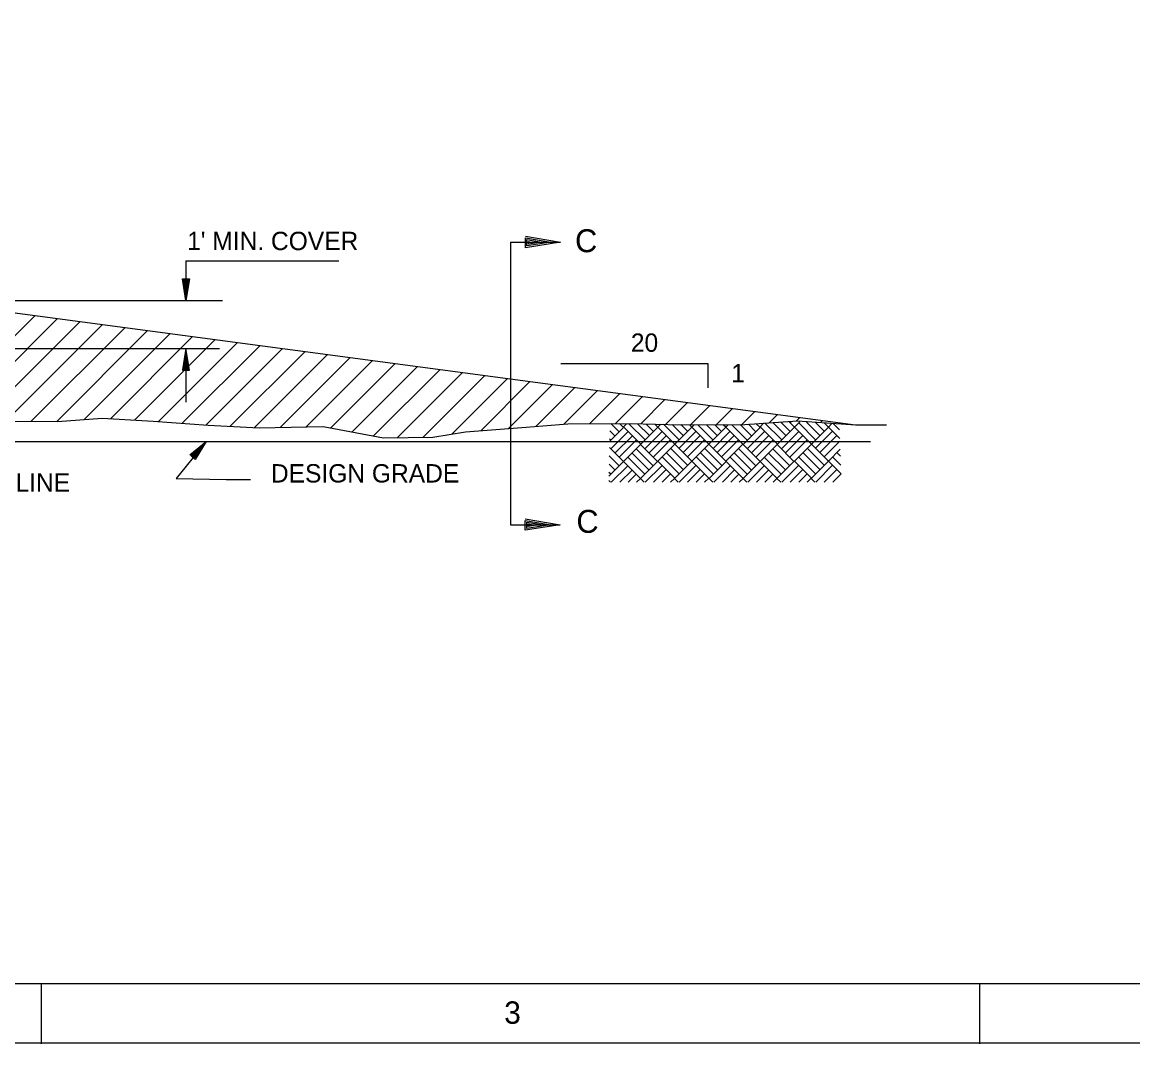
# Model space of a CAD drawing. Extents: x 2127959 to 2137375, y 2146193 to 2153470.
# Drawn here: x 2131601 to 2133592, y 2146193 to 2148025 of the extents above; entities that cross this region are included whole.
import ezdxf

# ---------------------------------------------------------------- set-up
doc = ezdxf.new("R2010")
doc.units = 0
for name, color, linetype in [('Level 1', 7, 'Continuous'), ('Level 3', 7, 'Continuous'), ('Level 5', 7, 'Continuous'), ('Level 50', 7, 'Continuous'), ('Level 63', 7, 'Continuous')]:
    doc.layers.add(name, color=color, linetype=linetype)

msp = doc.modelspace()

# ---------------------------------------------------------------- linework, layer by layer
at = {"layer": 'Level 1'}
for p, q in [((2131420.849, 2147525.847), (2133094.565, 2147302.516)), ((2129371.61, 2147272.911), (2133121.44, 2147272.911)), ((2128280.166, 2146300.478), (2136678.776, 2146300.478)), ((2131635.561, 2146192.625), (2131635.561, 2146300.478)), ((2133317.499, 2146192.626), (2133317.479, 2146300.478))]:
    msp.add_line(p, q, dxfattribs=at)
msp.add_lwpolyline([(2127959.193, 2153469.025), (2137374.681, 2153469.025), (2137374.681, 2146193.484), (2127959.193, 2146193.484)], close=True, dxfattribs=at)
at = {"layer": 'Level 3'}
for p, q in [((2131894.299, 2147597.059), (2131894.299, 2147525.847)), ((2131894.299, 2147597.059), (2132168.386, 2147597.059)), ((2131887.835, 2147564.595), (2131900.751, 2147564.595)), ((2131894.299, 2147525.847), (2131887.835, 2147564.595)), ((2131893.695, 2147563.956), (2131888.715, 2147564.052)), ((2131888.715, 2147564.052), (2131893.682, 2147533.841)), ((2131893.682, 2147563.213), (2131889.683, 2147563.324)), ((2131889.683, 2147563.324), (2131893.06, 2147541.295)), ((2131892.938, 2147562.359), (2131890.63, 2147562.448)), ((2131890.63, 2147562.448), (2131892.215, 2147551.348)), ((2131892.215, 2147551.348), (2131892.026, 2147561.706)), ((2131893.06, 2147541.295), (2131892.938, 2147562.359)), ((2131893.682, 2147533.841), (2131893.682, 2147563.213)), ((2131894.299, 2147525.847), (2131894.299, 2147564.595)), ((2131900.751, 2147564.595), (2131894.299, 2147525.847)), ((2131899.902, 2147563.937), (2131894.887, 2147533.753)), ((2131894.887, 2147533.753), (2131895.043, 2147563.205)), ((2131895.024, 2147564.01), (2131899.902, 2147563.937)), ((2131895.043, 2147563.205), (2131898.989, 2147563.077)), ((2131898.989, 2147563.077), (2131895.507, 2147541.148)), ((2131895.507, 2147541.148), (2131895.819, 2147562.373)), ((2131895.819, 2147562.373), (2131898.077, 2147562.382)), ((2131898.077, 2147562.382), (2131896.351, 2147551.367)), ((2131896.351, 2147551.367), (2131896.506, 2147561.72)), ((2131480.569, 2147525.847), (2131959.901, 2147525.847)), ((2131308.441, 2147439.647), (2131954.262, 2147439.647)), ((2131894.299, 2147439.647), (2131887.835, 2147400.893)), ((2131888.715, 2147401.44), (2131893.682, 2147431.65)), ((2131893.682, 2147431.65), (2131893.682, 2147402.277)), ((2131894.299, 2147439.647), (2131894.299, 2147343.107)), ((2131894.299, 2147439.647), (2131894.299, 2147400.893)), ((2131900.751, 2147400.893), (2131894.299, 2147439.647)), ((2131899.902, 2147401.557), (2131894.887, 2147431.738)), ((2131894.887, 2147431.738), (2131895.043, 2147402.288)), ((2131889.683, 2147402.166), (2131893.06, 2147424.198)), ((2131890.63, 2147403.041), (2131892.215, 2147414.142)), ((2131892.215, 2147414.142), (2131892.026, 2147403.786)), ((2131893.06, 2147424.198), (2131892.938, 2147403.133)), ((2131898.989, 2147402.417), (2131895.507, 2147424.345)), ((2131895.507, 2147424.345), (2131895.819, 2147403.116)), ((2131898.077, 2147403.107), (2131896.351, 2147414.125)), ((2131896.351, 2147414.125), (2131896.506, 2147403.773)), ((2132566.189, 2147412.463), (2132829.807, 2147412.463)), ((2132829.807, 2147412.463), (2132829.807, 2147369.047)), ((2131887.835, 2147400.893), (2131900.751, 2147400.893)), ((2131893.695, 2147401.534), (2131888.715, 2147401.44)), ((2131893.682, 2147402.277), (2131889.683, 2147402.166)), ((2131892.938, 2147403.133), (2131890.63, 2147403.041)), ((2131895.024, 2147401.481), (2131899.902, 2147401.557)), ((2131895.043, 2147402.288), (2131898.989, 2147402.417)), ((2131895.819, 2147403.116), (2131898.077, 2147403.107))]:
    msp.add_line(p, q, dxfattribs=at)
msp.add_lwpolyline([(2131930.575, 2147272.911), (2131876.766, 2147206.284), (2131966.089, 2147204.876), (2132009.879, 2147204.876)], dxfattribs=at)
at = {"layer": 'Level 5'}
for p, q in [((2131427.918, 2147302.868), (2131623.818, 2147498.766)), ((2131478.14, 2147307.381), (2131664.145, 2147493.383)), ((2131525.448, 2147308.965), (2131704.468, 2147488.002)), ((2131571.321, 2147309.125), (2131744.812, 2147482.62)), ((2131616.941, 2147309.031), (2131785.136, 2147477.238)), ((2131662.557, 2147308.933), (2131825.477, 2147471.859)), ((2131711.571, 2147312.24), (2131865.803, 2147466.473)), ((2131758.759, 2147313.709), (2131906.145, 2147461.091)), ((2131802.083, 2147311.32), (2131946.471, 2147455.711)), ((2131845.2, 2147308.727), (2131986.812, 2147450.331)), ((2131887.682, 2147305.486), (2132027.137, 2147444.951)), ((2131930.162, 2147302.244), (2132067.475, 2147439.565)), ((2131973.658, 2147300.023), (2132107.803, 2147434.184)), ((2132017.24, 2147297.902), (2132148.145, 2147428.8)), ((2132063.185, 2147298.138), (2132188.471, 2147423.419)), ((2132109.698, 2147298.925), (2132228.813, 2147418.037)), ((2132153.507, 2147297.026), (2132269.136, 2147412.656)), ((2132192.16, 2147289.963), (2132309.482, 2147407.275)), ((2132230.829, 2147282.904), (2132349.804, 2147401.892)), ((2132273.517, 2147279.887), (2132390.146, 2147396.509)), ((2132319.668, 2147280.323), (2132430.472, 2147391.131)), ((2132371.028, 2147285.972), (2132470.812, 2147385.748)), ((2132422.904, 2147292.129), (2132511.14, 2147380.366)), ((2132472.571, 2147296.078), (2132551.481, 2147374.984)), ((2132522.293, 2147300.078), (2132591.807, 2147369.602)), ((2132572.101, 2147304.177), (2132632.146, 2147364.221)), ((2132618.582, 2147304.944), (2132672.472, 2147358.836)), ((2132664.528, 2147305.173), (2132712.814, 2147353.455)), ((2132709.8, 2147304.731), (2132753.141, 2147348.076)), ((2132754.121, 2147303.349), (2132793.482, 2147342.692)), ((2132799.104, 2147302.603), (2132833.807, 2147337.31)), ((2132845.029, 2147302.825), (2132874.15, 2147331.928)), ((2131663.763, 2147308.929), (2131744.275, 2147314.507)), ((2131744.275, 2147314.507), (2131835.254, 2147309.487)), ((2132890.976, 2147303.046), (2132914.475, 2147326.547)), ((2132939.783, 2147306.131), (2132954.817, 2147321.165)), ((2132988.968, 2147309.618), (2132995.139, 2147315.784)), ((2131532.704, 2147309.209), (2131663.763, 2147308.929)), ((2131835.254, 2147309.487), (2131933.883, 2147301.958)), ((2131933.883, 2147301.958), (2132025.569, 2147297.499)), ((2132025.569, 2147297.499), (2132140.231, 2147299.448)), ((2132140.231, 2147299.448), (2132248.639, 2147279.652)), ((2132395.718, 2147289.967), (2132504.469, 2147298.615)), ((2132504.469, 2147298.615), (2132579.064, 2147304.744)), ((2132579.064, 2147304.744), (2132691.301, 2147305.304)), ((2132678.832, 2147297.918), (2132653.765, 2147272.855)), ((2132654.147, 2147292.113), (2132662.991, 2147283.279)), ((2132656.405, 2147305.093), (2132670.593, 2147290.892)), ((2132678.23, 2147298.516), (2132671.887, 2147304.85)), ((2132678.832, 2147299.136), (2132684.353, 2147304.657)), ((2132679.438, 2147298.537), (2132709.919, 2147268.06)), ((2132717.573, 2147275.66), (2132688.642, 2147304.592)), ((2132691.301, 2147305.304), (2132780.879, 2147302.516)), ((2132725.159, 2147283.298), (2132704.109, 2147304.355)), ((2132740.451, 2147298.537), (2132709.97, 2147268.06)), ((2132719.607, 2147304.114), (2132732.817, 2147290.909)), ((2132735.054, 2147303.878), (2132740.398, 2147298.537)), ((2132740.451, 2147298.537), (2132745.623, 2147303.708)), ((2132740.451, 2147298.537), (2132770.916, 2147268.06)), ((2132778.414, 2147275.813), (2132750.605, 2147303.626)), ((2132786.035, 2147283.428), (2132766.088, 2147303.373)), ((2132770.794, 2147268.181), (2132801.258, 2147298.659)), ((2132780.879, 2147302.516), (2132896.595, 2147303.076)), ((2132781.621, 2147303.118), (2132793.67, 2147291.065)), ((2132797.07, 2147302.867), (2132801.392, 2147298.537)), ((2132801.258, 2147298.659), (2132805.343, 2147302.729)), ((2132831.736, 2147268.181), (2132801.258, 2147298.659)), ((2132839.222, 2147275.65), (2132812.205, 2147302.669)), ((2132827.412, 2147302.743), (2132846.857, 2147283.287)), ((2132862.101, 2147298.525), (2132831.617, 2147268.051)), ((2132842.566, 2147302.814), (2132854.479, 2147290.904)), ((2132862.101, 2147298.525), (2132857.736, 2147302.887)), ((2132862.101, 2147298.525), (2132866.495, 2147302.931)), ((2132892.613, 2147268.051), (2132862.148, 2147298.525)), ((2132900.216, 2147275.65), (2132872.91, 2147302.96)), ((2132888.112, 2147303.036), (2132907.851, 2147283.287)), ((2132923.714, 2147297.929), (2132893.233, 2147267.451)), ((2132896.595, 2147303.076), (2132991.057, 2147309.766)), ((2132902.698, 2147303.677), (2132915.475, 2147290.904)), ((2132923.094, 2147298.525), (2132916.974, 2147304.655)), ((2132923.714, 2147299.148), (2132930.129, 2147305.56)), ((2132924.317, 2147298.545), (2132954.799, 2147268.069)), ((2132962.435, 2147275.672), (2132932.403, 2147305.713)), ((2132970.039, 2147283.311), (2132946.643, 2147306.693)), ((2132985.316, 2147298.545), (2132954.832, 2147268.069)), ((2132960.938, 2147307.672), (2132977.693, 2147290.921)), ((2132975.159, 2147308.648), (2132985.26, 2147298.545)), ((2132980.28, 2147308.756), (2132977.693, 2147306.171)), ((2132985.316, 2147298.545), (2132994.815, 2147308.041)), ((2132985.316, 2147298.545), (2133015.794, 2147268.069)), ((2132991.057, 2147309.766), (2133094.565, 2147302.516)), ((2133023.296, 2147275.821), (2132992.95, 2147306.171)), ((2133030.897, 2147283.436), (2133006.896, 2147307.446)), ((2133015.657, 2147268.194), (2133046.139, 2147298.67)), ((2133022.966, 2147306.654), (2133038.551, 2147291.074)), ((2133031.966, 2147306.899), (2133035.467, 2147310.404)), ((2133038.948, 2147305.863), (2133046.275, 2147298.545)), ((2133046.139, 2147298.67), (2133052.656, 2147305.186)), ((2133066.531, 2147278.272), (2133046.139, 2147298.67)), ((2133065.896, 2147293.861), (2133054.669, 2147305.089)), ((2133074.687, 2147303.906), (2133075.809, 2147305.02)), ((2133094.6, 2147302.511), (2133150.68, 2147302.795)), ((2132248.639, 2147279.652), (2132337.169, 2147280.486)), ((2132337.169, 2147280.486), (2132395.718, 2147289.967)), ((2132655.351, 2147275.643), (2132653.853, 2147277.132)), ((2132655.955, 2147259.792), (2132686.454, 2147290.292)), ((2132663.596, 2147252.201), (2132694.072, 2147282.682)), ((2132701.709, 2147275.045), (2132671.214, 2147244.539)), ((2132717.573, 2147260.411), (2132748.073, 2147290.909)), ((2132725.211, 2147252.82), (2132755.691, 2147283.298)), ((2132763.312, 2147275.66), (2132732.817, 2147245.159)), ((2132778.396, 2147260.583), (2132808.892, 2147291.082)), ((2132816.499, 2147283.424), (2132786.035, 2147252.946)), ((2132824.135, 2147275.831), (2132793.637, 2147245.332)), ((2132839.373, 2147260.556), (2132869.72, 2147290.904)), ((2132846.979, 2147252.94), (2132877.338, 2147283.287)), ((2132884.978, 2147275.65), (2132854.616, 2147245.303)), ((2132900.838, 2147259.797), (2132931.335, 2147290.301)), ((2132908.477, 2147252.213), (2132938.936, 2147282.688)), ((2132946.575, 2147275.052), (2132916.077, 2147244.553)), ((2132962.435, 2147260.42), (2132992.95, 2147290.921)), ((2132970.075, 2147252.832), (2133000.553, 2147283.309)), ((2133008.192, 2147275.671), (2132977.693, 2147245.171)), ((2133023.259, 2147260.592), (2133053.759, 2147291.092)), ((2133061.376, 2147283.432), (2133030.897, 2147252.955)), ((2133066.737, 2147273.562), (2133038.515, 2147245.343)), ((2132678.832, 2147236.916), (2132653.556, 2147262.193)), ((2132709.316, 2147267.443), (2132678.832, 2147236.961)), ((2132724.416, 2147221.804), (2132694.072, 2147252.154)), ((2132701.709, 2147259.792), (2132732.056, 2147229.445)), ((2132709.316, 2147267.392), (2132739.658, 2147237.044)), ((2132740.312, 2147237.707), (2132770.794, 2147268.192)), ((2132755.553, 2147252.946), (2132786.035, 2147222.469)), ((2132763.139, 2147260.583), (2132793.637, 2147230.081)), ((2132801.258, 2147237.707), (2132770.794, 2147268.181)), ((2132801.258, 2147237.707), (2132831.736, 2147268.181)), ((2132846.979, 2147222.469), (2132816.499, 2147252.946)), ((2132824.135, 2147260.583), (2132854.65, 2147230.081)), ((2132831.736, 2147268.181), (2132862.218, 2147237.707)), ((2132892.578, 2147268.051), (2132862.218, 2147237.702)), ((2132877.992, 2147252.162), (2132908.477, 2147221.685)), ((2132885.576, 2147259.798), (2132916.077, 2147229.301)), ((2132923.714, 2147236.925), (2132893.233, 2147267.402)), ((2132954.18, 2147267.451), (2132923.714, 2147236.976)), ((2132969.299, 2147221.816), (2132938.936, 2147252.162)), ((2132946.575, 2147259.798), (2132976.938, 2147229.451)), ((2132954.18, 2147267.402), (2132984.536, 2147237.053)), ((2132985.194, 2147237.713), (2133015.672, 2147268.197)), ((2133000.419, 2147252.955), (2133030.897, 2147222.477)), ((2133008.02, 2147260.592), (2133038.515, 2147230.09)), ((2133046.139, 2147237.713), (2133015.657, 2147268.194)), ((2133046.139, 2147237.713), (2133067.345, 2147258.914)), ((2133067.859, 2147246.483), (2133061.376, 2147252.955)), ((2132678.832, 2147236.916), (2132652.525, 2147210.615)), ((2132652.957, 2147232.306), (2132663.596, 2147221.677)), ((2132653.266, 2147247.238), (2132671.214, 2147229.289)), ((2132678.832, 2147236.916), (2132709.316, 2147206.435)), ((2132716.817, 2147214.191), (2132686.454, 2147244.539)), ((2132709.18, 2147206.564), (2132739.658, 2147237.039)), ((2132770.794, 2147207.23), (2132740.312, 2147237.707)), ((2132778.396, 2147214.832), (2132747.882, 2147245.332)), ((2132770.794, 2147207.181), (2132801.258, 2147237.661)), ((2132801.258, 2147237.707), (2132831.736, 2147207.23)), ((2132839.393, 2147214.832), (2132808.892, 2147245.332)), ((2132832.392, 2147206.58), (2132862.872, 2147237.058)), ((2132893.355, 2147206.58), (2132862.872, 2147237.058)), ((2132862.872, 2147237.058), (2132893.355, 2147206.58)), ((2132900.838, 2147214.052), (2132870.323, 2147244.553)), ((2132923.714, 2147236.925), (2132893.233, 2147206.451)), ((2132923.714, 2147236.925), (2132954.18, 2147206.451)), ((2132961.679, 2147214.203), (2132931.335, 2147244.553)), ((2132954.055, 2147206.57), (2132984.523, 2147237.05)), ((2133015.657, 2147207.238), (2132985.194, 2147237.713)), ((2133023.259, 2147214.84), (2132992.761, 2147245.343)), ((2133015.657, 2147207.192), (2133046.139, 2147237.667)), ((2133046.139, 2147237.713), (2133069.173, 2147214.689)), ((2133068.514, 2147230.599), (2133053.759, 2147245.343)), ((2132655.955, 2147214.04), (2132652.665, 2147217.335)), ((2132656.924, 2147199.749), (2132686.454, 2147229.289)), ((2132672.145, 2147199.749), (2132694.072, 2147221.677)), ((2132701.709, 2147214.04), (2132687.421, 2147199.749)), ((2132717.555, 2147199.749), (2132747.277, 2147229.459)), ((2132754.896, 2147221.801), (2132732.83, 2147199.749)), ((2132762.536, 2147214.211), (2132748.073, 2147199.749)), ((2132778.551, 2147199.749), (2132808.892, 2147230.081)), ((2132816.499, 2147222.419), (2132793.827, 2147199.749)), ((2132824.135, 2147214.832), (2132809.064, 2147199.749)), ((2132840.77, 2147199.749), (2132870.492, 2147229.482)), ((2132878.114, 2147221.822), (2132856.045, 2147199.749)), ((2132885.75, 2147214.229), (2132871.269, 2147199.749)), ((2132901.788, 2147199.749), (2132931.335, 2147229.301)), ((2132917.008, 2147199.749), (2132938.936, 2147221.685)), ((2132946.575, 2147214.052), (2132932.285, 2147199.749)), ((2132962.435, 2147199.749), (2132992.157, 2147229.472)), ((2132999.758, 2147221.809), (2132977.693, 2147199.749)), ((2133007.398, 2147214.222), (2132992.933, 2147199.749)), ((2133023.415, 2147199.749), (2133053.759, 2147230.09)), ((2133061.376, 2147222.426), (2133038.689, 2147199.749)), ((2133069.016, 2147214.84), (2133053.913, 2147199.749)), ((2132652.37, 2147202.677), (2132655.299, 2147199.749)), ((2132702.366, 2147199.749), (2132709.18, 2147206.564)), ((2132715.988, 2147199.749), (2132709.18, 2147206.564)), ((2132763.312, 2147199.749), (2132770.139, 2147206.564)), ((2132776.999, 2147199.749), (2132770.173, 2147206.564)), ((2132824.306, 2147199.749), (2132831.736, 2147207.181)), ((2132832.36, 2147206.58), (2132839.184, 2147199.749)), ((2132886.509, 2147199.749), (2132893.355, 2147206.58)), ((2132893.355, 2147206.58), (2132900.184, 2147199.749)), ((2132947.233, 2147199.749), (2132954.055, 2147206.57)), ((2132960.865, 2147199.749), (2132954.055, 2147206.57)), ((2133008.174, 2147199.749), (2133015.002, 2147206.57)), ((2133021.88, 2147199.749), (2133015.053, 2147206.57))]:
    msp.add_line(p, q, dxfattribs=at)
at = {"layer": 'Level 50'}
for p, q in [((2132548.341, 2147630.292), (2132548.341, 2147630.292)), ((2132565.806, 2147630.155), (2132565.806, 2147630.155)), ((2131930.487, 2147272.571), (2131930.487, 2147272.571)), ((2131923.697, 2147264.856), (2131923.697, 2147264.856)), ((2132547.998, 2147123.639), (2132547.998, 2147123.639)), ((2132565.463, 2147123.502), (2132565.463, 2147123.502))]:
    msp.add_line(p, q, dxfattribs=at)
for points in [[(2132503.065, 2147641.015), (2132565.806, 2147630.155), (2132502.939, 2147620.19), (2132503.062, 2147637.983), (2132548.341, 2147630.292), (2132505.661, 2147623.535), (2132505.723, 2147634.959), (2132531.55, 2147630.415), (2132508.362, 2147626.875), (2132508.387, 2147631.566), (2132514.082, 2147630.529)], [(2131901.441, 2147248.888), (2131930.487, 2147272.571), (2131910.651, 2147240.811), (2131902.77, 2147247.718), (2131923.697, 2147264.856), (2131910.208, 2147243.278), (2131905.151, 2147247.725), (2131917.148, 2147257.47), (2131909.763, 2147245.766), (2131907.678, 2147247.613), (2131910.356, 2147249.736)], [(2132502.722, 2147134.362), (2132565.463, 2147123.502), (2132502.596, 2147113.537), (2132502.719, 2147131.33), (2132547.998, 2147123.639), (2132505.318, 2147116.882), (2132505.38, 2147128.306), (2132531.207, 2147123.762), (2132508.019, 2147120.222), (2132508.044, 2147124.913), (2132513.739, 2147123.876)]]:
    msp.add_lwpolyline(points, dxfattribs=at)
at = {"layer": 'Level 63'}
for p, q in [((2132476.246, 2147630.155), (2132565.806, 2147630.155)), ((2132476.246, 2147630.155), (2132476.246, 2147123.502)), ((2132476.246, 2147123.502), (2132565.463, 2147123.502))]:
    msp.add_line(p, q, dxfattribs=at)

# ---------------------------------------------------------------- texts
at = {"layer": 'Level 1'}
for s, height, p in [("1' MIN. COVER", 32.931, (2131896.406, 2147616.026)), ('20', 32.931, (2132691.989, 2147433.677)), ('1', 32.931, (2132872.065, 2147378.915)), ('DESIGN GRADE', 32.931, (2132046.616, 2147199.251)), ('PIPELINE', 32.931, (2131488.379, 2147182.916)), ('3', 40.073, (2132464.975, 2146228.569))]:
    msp.add_text(s, height=height, dxfattribs=at).set_placement(p)
at = {"layer": 'Level 63'}
for p in [(2132591.963, 2147612.31), (2132594.392, 2147109.001)]:
    msp.add_text('C', height=41.164, dxfattribs=at).set_placement(p)

doc.saveas('drawing.dxf')
